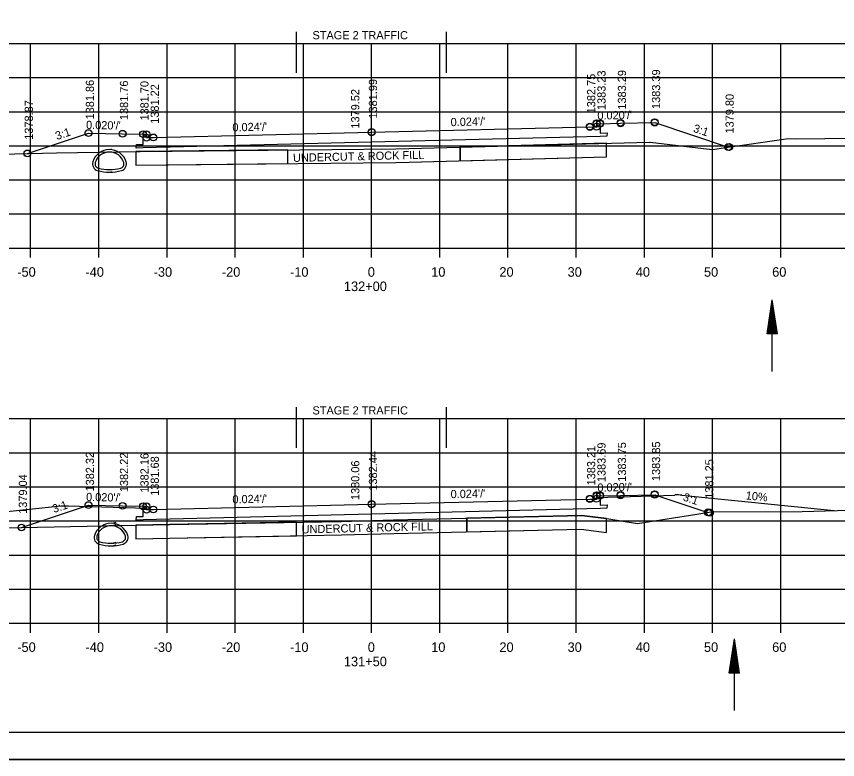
# Model space of a CAD drawing. Extents: x 1374311 to 1383814, y 384102 to 406278.
# Drawn here: x 1381576.6 to 1381697, y 387524.7 to 387633.6 of the extents above; entities that cross this region are included whole.
import ezdxf

# ---------------------------------------------------------------- set-up
doc = ezdxf.new("R2010")
doc.units = 0
for name, color, linetype in [('R_Axis', 7, 'Continuous'), ('R_Axis Annot', 7, 'Continuous'), ('R_Border', 7, 'Continuous'), ('R_Draft', 7, 'Continuous'), ('R_Exist Surface', 7, 'Continuous'), ('R_Fin Surface', 7, 'Continuous'), ('R_Grid', 7, 'Continuous'), ('R_No Plot', 7, 'Continuous'), ('R_Water', 7, 'Continuous'), ('R_Xsect Elev', 7, 'Continuous'), ('R_Xsect Slope', 7, 'Continuous')]:
    doc.layers.add(name, color=color, linetype=linetype)

msp = doc.modelspace()

# ---------------------------------------------------------------- linework, layer by layer
at = {"layer": 'R_Axis'}
for p, q in [((1381488.66, 387599.65), (1381768.66, 387599.65)), ((1381578.66, 387598.25), (1381578.66, 387599.65)), ((1381588.66, 387598.25), (1381588.66, 387599.65)), ((1381598.66, 387598.25), (1381598.66, 387599.65)), ((1381608.66, 387598.25), (1381608.66, 387599.65)), ((1381618.66, 387598.25), (1381618.66, 387599.65)), ((1381628.66, 387598.25), (1381628.66, 387599.65)), ((1381638.66, 387598.25), (1381638.66, 387599.65)), ((1381648.66, 387598.25), (1381648.66, 387599.65)), ((1381658.66, 387598.25), (1381658.66, 387599.65)), ((1381668.66, 387598.25), (1381668.66, 387599.65)), ((1381678.66, 387598.25), (1381678.66, 387599.65)), ((1381688.66, 387598.25), (1381688.66, 387599.65)), ((1381488.66, 387544.65), (1381768.66, 387544.65)), ((1381578.66, 387543.25), (1381578.66, 387544.65)), ((1381588.66, 387543.25), (1381588.66, 387544.65)), ((1381598.66, 387543.25), (1381598.66, 387544.65)), ((1381608.66, 387543.25), (1381608.66, 387544.65)), ((1381618.66, 387543.25), (1381618.66, 387544.65)), ((1381628.66, 387543.25), (1381628.66, 387544.65)), ((1381638.66, 387543.25), (1381638.66, 387544.65)), ((1381648.66, 387543.25), (1381648.66, 387544.65)), ((1381658.66, 387543.25), (1381658.66, 387544.65)), ((1381668.66, 387543.25), (1381668.66, 387544.65)), ((1381678.66, 387543.25), (1381678.66, 387544.65)), ((1381688.66, 387543.25), (1381688.66, 387544.65))]:
    msp.add_line(p, q, dxfattribs=at)
at = {"layer": 'R_Border'}
msp.add_line((1381786.84, 387528.65), (1381470.66, 387528.65), dxfattribs=at)
at = {"layer": 'R_Draft'}
for p, q in [((1381686.66, 387587.07), (1381687.41, 387592.07)), ((1381686.78, 387587.07), (1381687.41, 387591.24)), ((1381688.16, 387587.07), (1381687.41, 387592.07)), ((1381688.03, 387587.07), (1381687.41, 387591.24)), ((1381686.91, 387587.07), (1381687.41, 387590.38)), ((1381687.91, 387587.07), (1381687.41, 387590.38)), ((1381687.04, 387587.07), (1381687.41, 387589.55)), ((1381687.16, 387587.07), (1381687.41, 387588.7)), ((1381687.78, 387587.07), (1381687.41, 387589.55)), ((1381687.65, 387587.07), (1381687.41, 387588.7)), ((1381687.29, 387587.07), (1381687.41, 387587.86)), ((1381687.53, 387587.07), (1381687.41, 387587.86)), ((1381688.16, 387587.07), (1381686.66, 387587.07)), ((1381661.65, 387563.08), (1381673.12, 387563.45)), ((1381674.17, 387563.42), (1381696.49, 387561.19)), ((1381583.13, 387561.8), (1381546.15, 387558.1)), ((1381595.65, 387561.46), (1381584.19, 387561.83)), ((1381681.11, 387537.36), (1381681.86, 387542.36)), ((1381682.61, 387537.36), (1381681.86, 387542.36)), ((1381681.24, 387537.36), (1381681.86, 387541.52)), ((1381681.37, 387537.36), (1381681.86, 387540.66)), ((1381682.49, 387537.36), (1381681.86, 387541.52)), ((1381682.36, 387537.36), (1381681.86, 387540.66)), ((1381681.49, 387537.36), (1381681.86, 387539.83)), ((1381682.24, 387537.36), (1381681.86, 387539.83)), ((1381681.62, 387537.36), (1381681.86, 387538.98)), ((1381681.75, 387537.36), (1381681.86, 387538.15)), ((1381682.11, 387537.36), (1381681.86, 387538.98)), ((1381681.98, 387537.36), (1381681.86, 387538.15)), ((1381682.61, 387537.36), (1381681.11, 387537.36))]:
    msp.add_line(p, q, dxfattribs=at)
for centre, radius, start, end in [((1381590.22, 387611.54), 2.56, 17.1053, 162.8947), ((1381590.22, 387611.54), 2.19, 17.1053, 162.8947), ((1381588.75, 387611.99), 1.02, 162.8947, 254.2772), ((1381588.75, 387611.99), 0.646, 162.8947, 254.2772), ((1381591.69, 387611.99), 0.646, 285.7228, 17.1053), ((1381591.69, 387611.99), 1.02, 285.7228, 17.1053), ((1381590.22, 387617.23), 6.46, 254.2772, 285.7228), ((1381590.22, 387617.23), 6.08, 254.2772, 285.7228), ((1381673.38, 387555.46), 8, 84.2894, 91.854), ((1381583.93, 387553.84), 8, 88.146, 95.7106), ((1381590.46, 387556.77), 2.56, 17.1053, 162.8947), ((1381590.46, 387556.77), 2.19, 17.1053, 162.8947), ((1381588.99, 387557.23), 1.02, 162.8947, 254.2772), ((1381588.99, 387557.23), 0.646, 162.8947, 254.2772), ((1381591.93, 387557.23), 0.646, 285.7228, 17.1053), ((1381591.93, 387557.23), 1.02, 285.7228, 17.1053), ((1381590.46, 387562.46), 6.46, 254.2772, 285.7228), ((1381590.46, 387562.46), 6.08, 254.2772, 285.7228)]:
    msp.add_arc(centre, radius, start, end, dxfattribs=at)
at = {"layer": 'R_Exist Surface'}
for p, q in [((1381590.46, 387614.19), (1381590.46, 387614.05)), ((1381590.46, 387610.86), (1381590.46, 387610.71)), ((1381591.15, 387559.44), (1381590.63, 387559.29)), ((1381591.15, 387556.11), (1381590.63, 387555.96))]:
    msp.add_line(p, q, dxfattribs=at)
for points in [[(1381539.74, 387612.6), (1381582.47, 387613.63), (1381594.74, 387613.8), (1381632.2, 387614.21), (1381634.14, 387614.26), (1381669.42, 387615.19), (1381669.42, 387615.19), (1381669.5, 387615.18), (1381677.31, 387614.27), (1381678.64, 387614.12), (1381680.28, 387614.35), (1381689.78, 387615.71), (1381690.82, 387615.68), (1381695.1, 387615.74), (1381705.86, 387615.8), (1381727.26, 387616.6), (1381731.29, 387616.7), (1381737.47, 387616.82), (1381752.2, 387616.88), (1381752.29, 387616.88), (1381754.18, 387616.88), (1381767.14, 387616.91), (1381768.61, 387616.97), (1381768.66, 387616.97)], [(1381594.1, 387613.79), (1381594.1, 387611.79), (1381632.23, 387612.21), (1381634.19, 387612.26), (1381663.11, 387613.03), (1381663.12, 387615.03)], [(1381488.66, 387557.08), (1381513.26, 387557.47), (1381546.22, 387558.1), (1381574.82, 387558.64), (1381599.05, 387559.13), (1381624.19, 387559.59), (1381631.87, 387559.79), (1381659.48, 387560.46), (1381663.45, 387559.94), (1381667.65, 387559.29), (1381676.33, 387560.64), (1381678.43, 387560.97), (1381691.79, 387561.05), (1381698.7, 387561.25), (1381727.91, 387561.83), (1381732.96, 387561.84), (1381741.72, 387562.06), (1381747.39, 387562.07), (1381755.65, 387562.27), (1381760.86, 387562.57), (1381768.63, 387562.76), (1381768.66, 387562.76)], [(1381594.1, 387559.03), (1381594.09, 387557.03), (1381599.09, 387557.13), (1381624.23, 387557.6), (1381631.92, 387557.79), (1381659.37, 387558.46), (1381663.1, 387557.97), (1381663.11, 387560)]]:
    msp.add_lwpolyline(points, dxfattribs=at)
at = {"layer": 'R_Fin Surface'}
for p, q in [((1381616.36, 387614.04), (1381594.74, 387613.8)), ((1381616.36, 387612.04), (1381616.36, 387614.04)), ((1381616.36, 387612.04), (1381616.36, 387614.04)), ((1381663.12, 387615.03), (1381641.65, 387614.46)), ((1381641.65, 387612.46), (1381641.65, 387614.46)), ((1381641.65, 387614.46), (1381641.65, 387612.46)), ((1381663.11, 387613.03), (1381663.12, 387615.03)), ((1381594.74, 387613.8), (1381594.1, 387613.79)), ((1381641.65, 387612.46), (1381663.11, 387613.03)), ((1381642.64, 387558.05), (1381642.64, 387560.05)), ((1381642.64, 387560.05), (1381642.64, 387558.05)), ((1381599.05, 387559.13), (1381594.1, 387559.03)), ((1381617.63, 387559.47), (1381599.05, 387559.13)), ((1381617.63, 387557.47), (1381617.63, 387559.47)), ((1381617.63, 387557.47), (1381617.63, 387559.47)), ((1381642.64, 387558.05), (1381659.37, 387558.46))]:
    msp.add_line(p, q, dxfattribs=at)
for points in [[(1381578.19, 387613.53), (1381587.15, 387616.51), (1381592.15, 387616.41), (1381595.15, 387616.35), (1381595.65, 387616.35), (1381595.66, 387615.85), (1381596.66, 387615.87), (1381628.66, 387616.64), (1381660.66, 387617.41), (1381661.66, 387617.39), (1381661.67, 387617.89), (1381662.17, 387617.89), (1381665.17, 387617.95), (1381670.17, 387618.05), (1381680.96, 387614.45)], [(1381662.17, 387617.59), (1381662.18, 387616.51), (1381663.18, 387616.55), (1381663.17, 387616.05), (1381662.17, 387616.02), (1381628.66, 387615.18), (1381595.15, 387614.35), (1381594.15, 387614.32), (1381594.16, 387614.82), (1381595.16, 387614.83), (1381595.15, 387615.99)], [(1381594.1, 387613.79), (1381594.1, 387613.79)], [(1381594.1, 387613.79), (1381594.1, 387611.79), (1381616.36, 387612.04)], [(1381577.32, 387558.69), (1381587.15, 387561.97), (1381592.15, 387561.87), (1381595.15, 387561.81), (1381595.65, 387561.81), (1381595.66, 387561.31), (1381596.66, 387561.33), (1381628.66, 387562.1), (1381660.66, 387562.86), (1381661.66, 387562.84), (1381661.67, 387563.34), (1381662.17, 387563.34), (1381665.17, 387563.4), (1381670.17, 387563.5), (1381677.98, 387560.9)], [(1381662.17, 387563.05), (1381662.18, 387561.97), (1381663.18, 387562.01), (1381663.17, 387561.51), (1381662.17, 387561.48), (1381628.66, 387560.64), (1381595.15, 387559.81), (1381594.15, 387559.78), (1381594.16, 387560.28), (1381595.16, 387560.29), (1381595.15, 387561.45)], [(1381663.11, 387559.99), (1381663.11, 387559.99), (1381659.48, 387560.46), (1381642.64, 387560.05)], [(1381659.37, 387558.46), (1381663.1, 387557.97), (1381663.11, 387559.99)], [(1381594.1, 387559.03), (1381594.09, 387557.03), (1381599.09, 387557.13), (1381617.63, 387557.47)]]:
    msp.add_lwpolyline(points, dxfattribs=at)
at = {"layer": 'R_Grid'}
for p, q in [((1381488.66, 387629.65), (1381768.66, 387629.65)), ((1381578.66, 387599.65), (1381578.66, 387629.65)), ((1381588.66, 387599.65), (1381588.66, 387629.65)), ((1381598.66, 387599.65), (1381598.66, 387629.65)), ((1381608.66, 387599.65), (1381608.66, 387629.65)), ((1381618.66, 387599.65), (1381618.66, 387629.65)), ((1381628.66, 387599.65), (1381628.66, 387629.65)), ((1381638.66, 387599.65), (1381638.66, 387629.65)), ((1381648.66, 387599.65), (1381648.66, 387629.65)), ((1381658.66, 387599.65), (1381658.66, 387629.65)), ((1381668.66, 387599.65), (1381668.66, 387629.65)), ((1381678.66, 387599.65), (1381678.66, 387629.65)), ((1381688.66, 387599.65), (1381688.66, 387629.65)), ((1381488.66, 387624.65), (1381768.66, 387624.65)), ((1381488.66, 387619.65), (1381768.66, 387619.65)), ((1381488.66, 387614.65), (1381768.66, 387614.65)), ((1381488.66, 387609.65), (1381768.66, 387609.65)), ((1381488.66, 387604.65), (1381768.66, 387604.65)), ((1381488.66, 387599.65), (1381768.66, 387599.65)), ((1381488.66, 387574.65), (1381768.66, 387574.65)), ((1381578.66, 387544.65), (1381578.66, 387574.65)), ((1381588.66, 387544.65), (1381588.66, 387574.65)), ((1381598.66, 387544.65), (1381598.66, 387574.65)), ((1381608.66, 387544.65), (1381608.66, 387574.65)), ((1381618.66, 387544.65), (1381618.66, 387574.65)), ((1381628.66, 387544.65), (1381628.66, 387574.65)), ((1381638.66, 387544.65), (1381638.66, 387574.65)), ((1381648.66, 387544.65), (1381648.66, 387574.65)), ((1381658.66, 387544.65), (1381658.66, 387574.65)), ((1381668.66, 387544.65), (1381668.66, 387574.65)), ((1381678.66, 387544.65), (1381678.66, 387574.65)), ((1381688.66, 387544.65), (1381688.66, 387574.65)), ((1381488.66, 387569.65), (1381768.66, 387569.65)), ((1381488.66, 387564.65), (1381768.66, 387564.65)), ((1381488.66, 387559.65), (1381768.66, 387559.65)), ((1381488.66, 387554.65), (1381768.66, 387554.65)), ((1381488.66, 387549.65), (1381768.66, 387549.65)), ((1381488.66, 387544.65), (1381768.66, 387544.65))]:
    msp.add_line(p, q, dxfattribs=at)
at = {"layer": 'R_No Plot'}
msp.add_line((1381458.26, 387524.67), (1381791.59, 387524.67), dxfattribs=at)
for points in [[(1381458.25, 387738.01), (1381791.59, 387738.01), (1381791.59, 387524.67), (1381458.25, 387524.67)], [(1381704.58, 387734.11), (1381704.58, 387724.23), (1381740.31, 387724.23), (1381740.31, 387721.31), (1381763.51, 387721.31), (1381763.51, 387698.1), (1381786.84, 387698.1), (1381786.84, 387528.65), (1381470.66, 387528.65), (1381470.66, 387734.11)]]:
    msp.add_lwpolyline(points, close=True, dxfattribs=at)
for centre in [(1381660.65, 387617.47), (1381660.66, 387617.47), (1381660.66, 387617.41), (1381661.66, 387617.95), (1381661.66, 387617.45), (1381661.67, 387617.95), (1381661.67, 387617.89), (1381662.16, 387617.95), (1381662.17, 387617.95), (1381662.17, 387617.89), (1381665.16, 387618.01), (1381665.17, 387618.01), (1381665.17, 387617.95), (1381670.16, 387618.11), (1381670.17, 387618.11), (1381670.17, 387618.05), (1381587.14, 387616.51), (1381587.15, 387616.51), (1381587.15, 387616.51), (1381592.14, 387616.41), (1381592.15, 387616.41), (1381592.15, 387616.41), (1381595.14, 387616.35), (1381595.15, 387616.35), (1381595.15, 387616.35), (1381595.64, 387616.35), (1381595.65, 387616.35), (1381595.65, 387616.35), (1381596.65, 387615.87), (1381596.66, 387615.87), (1381596.66, 387615.87), (1381628.65, 387616.67), (1381628.66, 387616.67), (1381628.66, 387616.64), (1381595.66, 387615.85), (1381578.18, 387613.52), (1381578.18, 387613.52), (1381578.19, 387613.53), (1381578.19, 387613.53), (1381578.19, 387613.53), (1381578.19, 387613.53), (1381680.96, 387614.45), (1381681.07, 387614.47), (1381681.1, 387614.47), (1381660.65, 387562.93), (1381660.66, 387562.93), (1381661.66, 387563.41), (1381661.66, 387562.91), (1381661.67, 387563.41), (1381661.67, 387563.34), (1381662.16, 387563.41), (1381662.17, 387563.41), (1381662.17, 387563.34), (1381665.16, 387563.47), (1381665.17, 387563.47), (1381665.17, 387563.4), (1381670.16, 387563.57), (1381670.17, 387563.57), (1381670.17, 387563.5), (1381587.14, 387561.97), (1381587.15, 387561.97), (1381587.15, 387561.97), (1381592.14, 387561.87), (1381592.15, 387561.87), (1381592.15, 387561.87), (1381595.14, 387561.81), (1381595.15, 387561.81), (1381595.15, 387561.81), (1381595.64, 387561.81), (1381595.65, 387561.81), (1381595.65, 387561.81), (1381628.65, 387562.13), (1381628.66, 387562.13), (1381628.66, 387562.1), (1381660.66, 387562.86), (1381595.66, 387561.31), (1381596.65, 387561.33), (1381596.66, 387561.33), (1381596.66, 387561.33), (1381677.98, 387560.9), (1381678.12, 387560.92), (1381678.27, 387560.87), (1381577.32, 387558.69), (1381577.32, 387558.69), (1381577.32, 387558.69), (1381577.32, 387558.69), (1381577.32, 387558.69), (1381577.32, 387558.69)]:
    msp.add_circle(centre, 0.5, dxfattribs=at)
at = {"layer": 'R_Water'}
for p, q in [((1381617.64, 387625.35), (1381617.64, 387631.35)), ((1381639.64, 387625.35), (1381639.64, 387631.35)), ((1381617.63, 387629.65), (1381639.68, 387629.65)), ((1381590.46, 387613.82), (1381590.46, 387613.67)), ((1381590.46, 387611.23), (1381590.46, 387611.09)), ((1381687.41, 387581.57), (1381687.41, 387592.07)), ((1381617.64, 387570.35), (1381617.64, 387576.35)), ((1381639.64, 387570.35), (1381639.64, 387576.35)), ((1381617.63, 387574.65), (1381639.68, 387574.65)), ((1381591.15, 387559.06), (1381590.63, 387558.92)), ((1381591.15, 387556.48), (1381590.63, 387556.33)), ((1381681.86, 387531.85), (1381681.86, 387542.36))]:
    msp.add_line(p, q, dxfattribs=at)

# ---------------------------------------------------------------- texts
at = {"layer": 'R_Axis Annot'}
for s, p in [('-50', (1381576.7, 387595.45)), ('-40', (1381586.7, 387595.45)), ('-30', (1381596.7, 387595.45)), ('-20', (1381606.7, 387595.45)), ('-10', (1381616.7, 387595.45)), ('0', (1381628.1, 387595.45)), ('10', (1381637.4, 387595.45)), ('20', (1381647.4, 387595.45)), ('30', (1381657.4, 387595.45)), ('40', (1381667.4, 387595.45)), ('50', (1381677.4, 387595.45)), ('60', (1381687.4, 387595.45)), ('132+00', (1381624.6, 387593.35)), ('-50', (1381576.7, 387540.45)), ('-40', (1381586.7, 387540.45)), ('-30', (1381596.7, 387540.45)), ('-20', (1381606.7, 387540.45)), ('-10', (1381616.7, 387540.45)), ('0', (1381628.1, 387540.45)), ('10', (1381637.4, 387540.45)), ('20', (1381647.4, 387540.45)), ('30', (1381657.4, 387540.45)), ('40', (1381667.4, 387540.45)), ('50', (1381677.4, 387540.45)), ('60', (1381687.4, 387540.45)), ('131+50', (1381624.6, 387538.35))]:
    msp.add_text(s, height=1.4, dxfattribs=at).set_placement(p)
at = {"layer": 'R_Draft'}
msp.add_text('10%', height=1.2, rotation=354.2894, dxfattribs=at).set_placement((1381683.48, 387562.82))
at = {"layer": 'R_Fin Surface'}
for p in [(1381617.15, 387612.28), (1381618.41, 387557.81)]:
    msp.add_text('UNDERCUT & ROCK FILL', height=1.2, rotation=1.3914, dxfattribs=at).set_placement(p)
at = {"layer": 'R_Water'}
for p in [(1381619.99, 387630.26), (1381619.99, 387575.26)]:
    msp.add_text('STAGE 2 TRAFFIC', height=1.2, dxfattribs=at).set_placement(p)
at = {"layer": 'R_Xsect Elev'}
for s, p in [('1382.75', (1381661.46, 387619.41)), ('1383.23', (1381662.97, 387619.89)), ('1383.29', (1381665.97, 387619.95)), ('1383.39', (1381670.97, 387620.05)), ('1381.86', (1381587.95, 387618.51)), ('1381.76', (1381592.95, 387618.41)), ('1381.70', (1381595.95, 387618.35)), ('1381.22', (1381597.46, 387617.87)), ('1381.99', (1381629.46, 387618.64)), ('1379.52', (1381626.86, 387617.17)), ('1378.87', (1381578.99, 387615.53)), ('1379.80', (1381681.76, 387616.45)), ('1383.69', (1381662.97, 387565.34)), ('1383.75', (1381665.97, 387565.4)), ('1383.85', (1381670.97, 387565.5)), ('1382.32', (1381587.95, 387563.97)), ('1382.22', (1381592.95, 387563.87)), ('1382.16', (1381595.95, 387563.81)), ('1382.44', (1381629.46, 387564.1)), ('1383.21', (1381661.46, 387564.86)), ('1381.68', (1381597.46, 387563.33)), ('1380.06', (1381626.86, 387562.71)), ('1381.25', (1381678.78, 387562.9)), ('1379.04', (1381578.12, 387560.69))]:
    msp.add_text(s, height=1.2, rotation=90, dxfattribs=at).set_placement(p)
at = {"layer": 'R_Xsect Slope'}
for s, rotation, p in [("0.024'/'", 1.3748, (1381640.26, 387617.52)), ("0.020'/'", 1.1458, (1381661.78, 387618.48)), ("0.020'/'", 358.8542, (1381586.78, 387617.12)), ("0.024'/'", 1.3748, (1381608.26, 387616.75)), ('3:1', 341.5651, (1381675.72, 387616.72)), ('3:1', 18.4349, (1381582.51, 387615.49)), ("0.020'/'", 1.1458, (1381661.78, 387563.94)), ("0.020'/'", 358.8542, (1381586.78, 387562.58)), ("0.024'/'", 1.3748, (1381608.26, 387562.21)), ("0.024'/'", 1.3748, (1381640.26, 387562.98)), ('3:1', 341.5651, (1381674.23, 387562.68)), ('3:1', 18.4349, (1381582.08, 387560.81))]:
    msp.add_text(s, height=1.2, rotation=rotation, dxfattribs=at).set_placement(p)

doc.saveas('drawing.dxf')
